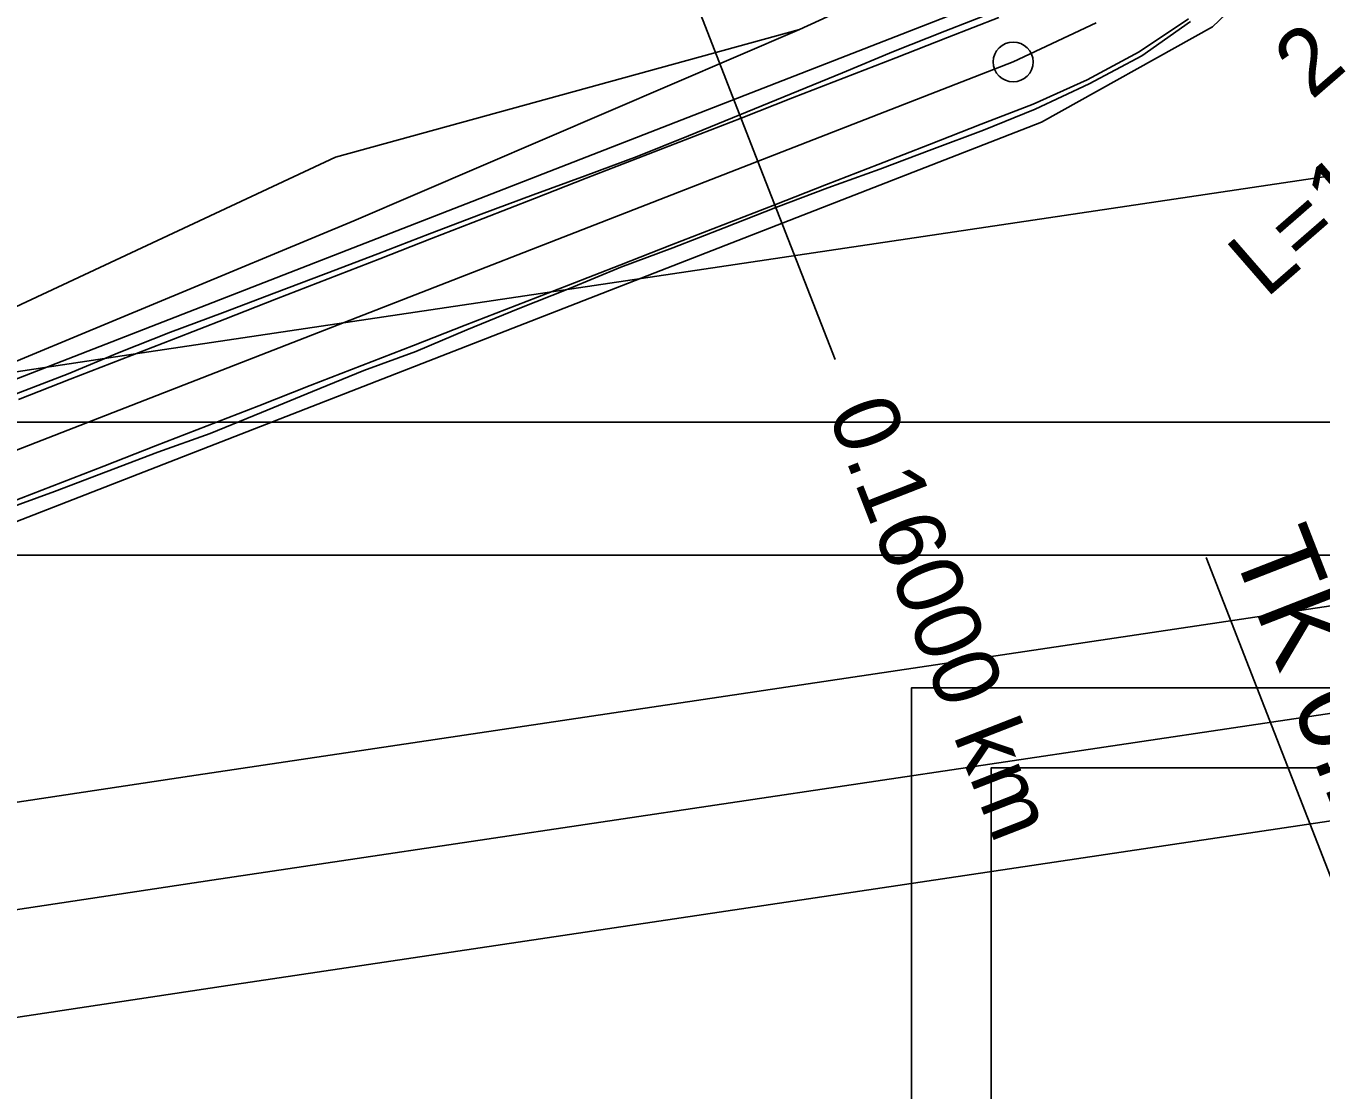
# Model space of a CAD drawing. Extents: x -555887 to -552101, y -1100251 to -1096546.
# Drawn here: x -554065.95 to -554017.23, y -1096790.84 to -1096750.82 of the extents above; entities that cross this region are included whole.
import ezdxf

# ---------------------------------------------------------------- set-up
doc = ezdxf.new("R2010")
doc.units = 0
for name, color, linetype in [('07_OCH_P A POPISY TI', 7, 'Continuous'), ('07_PLYNOVOD', 7, 'Continuous'), ('PARCELY_cesty', 7, 'Continuous'), ('POLYGONY_SITUACE_PF', 7, 'Continuous'), ('POLYGONY_SITUACE_PF_POPISY', 7, 'Continuous'), ('POLYGONY_SITUACE_PO', 7, 'Continuous'), ('ram_VC6', 7, 'Continuous'), ('ZSST', 7, 'Continuous')]:
    doc.layers.add(name, color=color, linetype=linetype)

msp = doc.modelspace()

# ---------------------------------------------------------------- linework, layer by layer
msp.add_line((-554021.556, -1096770.813), (-554013.902, -1096790.467))
at = {"layer": '07_OCH_P A POPISY TI'}
msp.add_lwpolyline([(-554130.516, -1096773.525), (-554061.917, -1096763.171), (-553969.228, -1096749.349), (-553879.887, -1096736.04), (-553864.66, -1096733.645), (-553882.5, -1096776.871), (-553963.332, -1096788.911), (-554055.983, -1096802.729), (-554135.075, -1096814.666)], dxfattribs=at)
msp.add_lwpolyline([(-554152.604, -1096784.878), (-554208.413, -1096768.467), (-554202.277, -1096761.933), (-554150.138, -1096777.264), (-554149.469, -1096777.303), (-554148.05, -1096777.984), (-554147.522, -1096778.568), (-554137.256, -1096789.931), (-554136.597, -1096790.624), (-554059.543, -1096778.994), (-553966.87, -1096765.174), (-553877.465, -1096751.856), (-553871.809, -1096750.966), (-553875.383, -1096759.627), (-553876.255, -1096759.764), (-553965.69, -1096773.086), (-554058.357, -1096786.906), (-554137.463, -1096798.845), (-554137.94, -1096798.917), (-554138.901, -1096798.83), (-554139.814, -1096798.517), (-554140.626, -1096797.996), (-554140.959, -1096797.646), (-554143.124, -1096795.369)], close=True, dxfattribs=at)
at = {"layer": '07_PLYNOVOD'}
msp.add_lwpolyline([(-553873.596, -1096755.297), (-553876.86, -1096755.81), (-553966.28, -1096769.13), (-554058.95, -1096782.95), (-554138.06, -1096794.89), (-554140.19, -1096792.65), (-554150.49, -1096781.25), (-554150.83, -1096781.23), (-554205.345, -1096765.2)], dxfattribs=at)
at = {"layer": 'PARCELY_cesty'}
for points in [[(-554174.9, -1096838.86), (-554167.64, -1096831.88), (-554135.583, -1096801.115), (-554129.606, -1096795.741), (-554116.704, -1096786.258), (-554106.195, -1096780.331), (-554095.284, -1096775.378), (-554029.882, -1096749.909), (-554024.308, -1096746.797), (-554020.974, -1096743.614), (-554018.176, -1096739.734), (-554005.148, -1096716.478), (-553996.738, -1096709.171), (-553992.165, -1096705.876), (-553986.987, -1096703.39), (-553981.451, -1096701.854), (-553975.732, -1096701.317), (-553970.007, -1096701.795), (-553964.395, -1096703.289), (-553952.141, -1096709.778)], [(-554168.999, -1096840.134), (-554132.179, -1096804.778), (-554126.446, -1096799.624), (-554113.985, -1096790.465), (-554103.93, -1096784.793), (-554093.342, -1096779.988), (-554027.746, -1096754.443), (-554021.315, -1096750.852), (-554017.188, -1096746.913), (-554013.953, -1096742.427), (-554001.212, -1096719.682), (-553993.63, -1096713.095), (-553989.602, -1096710.191), (-553985.223, -1096708.089), (-553980.542, -1096706.791), (-553975.706, -1096706.337), (-553970.865, -1096706.741), (-553966.232, -1096707.974), (-553954.851, -1096714.001)]]:
    msp.add_lwpolyline(points, dxfattribs=at)
at = {"layer": 'POLYGONY_SITUACE_PF'}
for p, q in [((-554041.317, -1096748.46), (-554038.414, -1096755.915)), ((-554038.414, -1096755.915), (-554035.511, -1096763.369))]:
    msp.add_line(p, q, dxfattribs=at)
at = {"layer": 'POLYGONY_SITUACE_PO'}
for p, q in [((-554031.379, -1096751.015), (-554029.447, -1096750.261)), ((-554031.284, -1096751.26), (-554029.351, -1096750.504)), ((-554031.284, -1096751.26), (-554029.351, -1096750.504)), ((-554024.073, -1096751.789), (-554022.217, -1096750.554)), ((-554024.073, -1096751.789), (-554022.217, -1096750.554)), ((-554033.314, -1096751.787), (-554031.379, -1096751.015)), ((-554028.814, -1096752.176), (-554025.697, -1096750.707)), ((-554023.977, -1096751.948), (-554022.143, -1096750.658)), ((-554033.225, -1096752.016), (-554031.284, -1096751.26)), ((-554033.225, -1096752.016), (-554031.284, -1096751.26)), ((-554035.239, -1096752.585), (-554033.314, -1096751.787)), ((-554035.166, -1096752.772), (-554033.225, -1096752.016)), ((-554035.166, -1096752.772), (-554033.225, -1096752.016)), ((-554026.03, -1096752.853), (-554024.073, -1096751.789)), ((-554026.03, -1096752.853), (-554024.073, -1096751.789)), ((-554025.957, -1096753.001), (-554023.977, -1096751.948)), ((-554094.313, -1096777.683), (-554028.814, -1096752.176)), ((-554037.167, -1096753.375), (-554035.239, -1096752.585)), ((-554037.108, -1096753.528), (-554035.166, -1096752.772)), ((-554037.108, -1096753.528), (-554035.166, -1096752.772)), ((-554028.066, -1096753.76), (-554026.03, -1096752.853)), ((-554028.066, -1096753.76), (-554026.03, -1096752.853)), ((-554027.989, -1096753.955), (-554025.957, -1096753.001)), ((-554039.095, -1096754.164), (-554037.167, -1096753.375)), ((-554039.049, -1096754.284), (-554037.108, -1096753.528)), ((-554039.049, -1096754.284), (-554037.108, -1096753.528)), ((-554030.013, -1096754.521), (-554028.066, -1096753.76)), ((-554030.013, -1096754.521), (-554028.066, -1096753.76)), ((-554029.93, -1096754.736), (-554027.989, -1096753.955)), ((-554041.025, -1096754.95), (-554039.095, -1096754.164)), ((-554040.99, -1096755.04), (-554039.049, -1096754.284)), ((-554040.99, -1096755.04), (-554039.049, -1096754.284)), ((-554042.958, -1096755.728), (-554041.025, -1096754.95)), ((-554031.955, -1096755.277), (-554030.013, -1096754.521)), ((-554031.955, -1096755.277), (-554030.013, -1096754.521)), ((-554031.879, -1096755.471), (-554029.93, -1096754.736)), ((-554042.932, -1096755.796), (-554040.99, -1096755.04)), ((-554042.932, -1096755.796), (-554040.99, -1096755.04)), ((-554033.896, -1096756.033), (-554031.955, -1096755.277)), ((-554033.896, -1096756.033), (-554031.955, -1096755.277)), ((-554033.83, -1096756.203), (-554031.879, -1096755.471)), ((-554044.91, -1096756.456), (-554042.958, -1096755.728)), ((-554044.873, -1096756.552), (-554042.932, -1096755.796)), ((-554044.873, -1096756.552), (-554042.932, -1096755.796)), ((-554046.866, -1096757.176), (-554044.91, -1096756.456)), ((-554035.837, -1096756.789), (-554033.896, -1096756.033)), ((-554035.837, -1096756.789), (-554033.896, -1096756.033)), ((-554035.79, -1096756.911), (-554033.83, -1096756.203)), ((-554046.814, -1096757.308), (-554044.873, -1096756.552)), ((-554046.814, -1096757.308), (-554044.873, -1096756.552)), ((-554037.779, -1096757.545), (-554035.837, -1096756.789)), ((-554037.779, -1096757.545), (-554035.837, -1096756.789)), ((-554037.738, -1096757.651), (-554035.79, -1096756.911)), ((-554048.82, -1096757.899), (-554046.866, -1096757.176)), ((-554048.755, -1096758.064), (-554046.814, -1096757.308)), ((-554048.755, -1096758.064), (-554046.814, -1096757.308)), ((-554050.768, -1096758.638), (-554048.82, -1096757.899)), ((-554039.72, -1096758.301), (-554037.779, -1096757.545)), ((-554039.72, -1096758.301), (-554037.779, -1096757.545)), ((-554039.678, -1096758.41), (-554037.738, -1096757.651)), ((-554050.697, -1096758.82), (-554048.755, -1096758.064)), ((-554050.697, -1096758.82), (-554048.755, -1096758.064)), ((-554041.661, -1096759.057), (-554039.72, -1096758.301)), ((-554041.661, -1096759.057), (-554039.72, -1096758.301)), ((-554041.62, -1096759.164), (-554039.678, -1096758.41)), ((-554052.711, -1096759.39), (-554050.768, -1096758.638)), ((-554052.638, -1096759.576), (-554050.697, -1096758.82)), ((-554052.638, -1096759.576), (-554050.697, -1096758.82)), ((-554043.603, -1096759.813), (-554041.661, -1096759.057)), ((-554043.603, -1096759.813), (-554041.661, -1096759.057)), ((-554043.571, -1096759.895), (-554041.62, -1096759.164)), ((-554054.656, -1096760.135), (-554052.711, -1096759.39)), ((-554054.579, -1096760.332), (-554052.638, -1096759.576)), ((-554054.579, -1096760.332), (-554052.638, -1096759.576)), ((-554045.544, -1096760.569), (-554043.603, -1096759.813)), ((-554045.544, -1096760.569), (-554043.603, -1096759.813)), ((-554056.605, -1096760.873), (-554054.656, -1096760.135)), ((-554056.521, -1096761.088), (-554054.579, -1096760.332)), ((-554056.521, -1096761.088), (-554054.579, -1096760.332)), ((-554045.496, -1096760.693), (-554043.571, -1096759.895)), ((-554047.485, -1096761.325), (-554045.544, -1096760.569)), ((-554047.485, -1096761.325), (-554045.544, -1096760.569)), ((-554047.431, -1096761.466), (-554045.496, -1096760.693)), ((-554058.553, -1096761.611), (-554056.605, -1096760.873)), ((-554058.462, -1096761.844), (-554056.521, -1096761.088)), ((-554058.462, -1096761.844), (-554056.521, -1096761.088)), ((-554049.427, -1096762.081), (-554047.485, -1096761.325)), ((-554049.427, -1096762.081), (-554047.485, -1096761.325)), ((-554060.508, -1096762.335), (-554058.553, -1096761.611)), ((-554049.359, -1096762.256), (-554047.431, -1096761.466)), ((-554060.403, -1096762.6), (-554058.462, -1096761.844)), ((-554060.403, -1096762.6), (-554058.462, -1096761.844)), ((-554051.368, -1096762.837), (-554049.427, -1096762.081)), ((-554051.368, -1096762.837), (-554049.427, -1096762.081)), ((-554051.278, -1096763.069), (-554049.359, -1096762.256)), ((-554062.446, -1096763.097), (-554060.508, -1096762.335)), ((-554062.345, -1096763.356), (-554060.403, -1096762.6)), ((-554062.345, -1096763.356), (-554060.403, -1096762.6)), ((-554064.366, -1096763.906), (-554062.446, -1096763.097)), ((-554053.309, -1096763.593), (-554051.368, -1096762.837)), ((-554053.309, -1096763.593), (-554051.368, -1096762.837)), ((-554053.235, -1096763.785), (-554051.278, -1096763.069)), ((-554064.286, -1096764.112), (-554062.345, -1096763.356)), ((-554064.286, -1096764.112), (-554062.345, -1096763.356)), ((-554055.251, -1096764.349), (-554053.309, -1096763.593)), ((-554055.251, -1096764.349), (-554053.309, -1096763.593)), ((-554066.311, -1096764.653), (-554064.366, -1096763.906)), ((-554066.227, -1096764.868), (-554064.286, -1096764.112)), ((-554066.227, -1096764.868), (-554064.286, -1096764.112)), ((-554055.163, -1096764.575), (-554053.235, -1096763.785)), ((-554057.192, -1096765.105), (-554055.251, -1096764.349)), ((-554057.192, -1096765.105), (-554055.251, -1096764.349)), ((-554057.091, -1096765.365), (-554055.163, -1096764.575)), ((-554059.133, -1096765.861), (-554057.192, -1096765.105)), ((-554059.133, -1096765.861), (-554057.192, -1096765.105)), ((-554059.019, -1096766.155), (-554057.091, -1096765.365)), ((-554061.075, -1096766.617), (-554059.133, -1096765.861)), ((-554061.075, -1096766.617), (-554059.133, -1096765.861)), ((-554060.982, -1096766.855), (-554059.019, -1096766.155)), ((-554063.016, -1096767.373), (-554061.075, -1096766.617)), ((-554063.016, -1096767.373), (-554061.075, -1096766.617)), ((-554062.929, -1096767.596), (-554060.982, -1096766.855)), ((-554064.957, -1096768.129), (-554063.016, -1096767.373)), ((-554064.957, -1096768.129), (-554063.016, -1096767.373)), ((-554064.88, -1096768.329), (-554062.929, -1096767.596)), ((-554066.899, -1096768.885), (-554064.957, -1096768.129)), ((-554066.899, -1096768.885), (-554064.957, -1096768.129)), ((-554066.836, -1096769.047), (-554064.88, -1096768.329))]:
    msp.add_line(p, q, dxfattribs=at)
msp.add_circle((-554028.814, -1096752.176), 0.75, dxfattribs=at)
at = {"layer": 'ram_VC6'}
for points in [[(-553956.64, -1096765.72), (-554313.64, -1096765.72), (-554313.64, -1097395.72), (-553956.64, -1097395.72)], [(-553961.64, -1096770.72), (-554308.64, -1096770.72), (-554308.64, -1097390.72), (-553961.64, -1097390.72)], [(-554032.64, -1096961.72), (-554032.64, -1096775.72), (-553966.64, -1096775.72), (-553966.64, -1096961.72)], [(-554029.64, -1096958.72), (-554029.64, -1096778.72), (-553969.64, -1096778.72), (-553969.64, -1096958.72)]]:
    msp.add_lwpolyline(points, close=True, dxfattribs=at)
for points in [[(-553956.64, -1096765.72), (-554313.64, -1096765.72), (-554313.64, -1097395.72), (-553956.64, -1097395.72), (-553956.64, -1096765.72)], [(-553956.64, -1096765.72), (-554313.64, -1096765.72), (-554313.64, -1097395.72), (-553956.64, -1097395.72), (-553956.64, -1096765.72)], [(-553961.64, -1097390.72), (-554308.64, -1097390.72), (-554308.64, -1096770.72), (-553961.64, -1096770.72), (-553961.64, -1097390.72)], [(-553961.64, -1097185.72), (-553961.64, -1097390.72), (-554308.64, -1097390.72), (-554308.64, -1096770.72), (-553961.64, -1096770.72), (-553961.64, -1096975.72), (-553961.64, -1097185.72)]]:
    msp.add_lwpolyline(points, dxfattribs=at)
at = {"layer": 'ZSST'}
for points in [[(-554009.12, -1096721.56), (-554015.18, -1096729.9), (-554024.59, -1096743.78), (-554029.87, -1096747.74), (-554036.85, -1096750.95), (-554054.31, -1096755.76), (-554076.78, -1096766.28), (-554100.4, -1096774.5), (-554109.57, -1096777.34), (-554130, -1096792.74), (-554141.88, -1096803.78), (-554155.75, -1096815.27)], [(-554160.46, -1096823.12), (-554154.41, -1096816.61), (-554141.11, -1096804.53), (-554129.31, -1096793.72), (-554108.05, -1096779.54), (-554099.77, -1096775.93), (-554076.23, -1096767.55), (-554053.62, -1096758.15), (-554036.85, -1096750.95)]]:
    msp.add_lwpolyline(points, dxfattribs=at)

# ---------------------------------------------------------------- texts
for s, height, rotation, p in [('L=17.241', 2.5, 41.0338, (-554019.305, -1096761.097)), ('2', 2.5, 41.0338, (-554017.588, -1096753.637)), ('TK 0.17030', 3, 291.2773, (-554020.624, -1096770.45))]:
    msp.add_text(s, height=height, rotation=rotation).set_placement(p)
at = {"layer": 'POLYGONY_SITUACE_PF_POPISY'}
msp.add_text('0.16000 km', height=2.5, rotation=291.2773, dxfattribs=at).set_placement((-554035.806, -1096765.366))

doc.saveas('drawing.dxf')
